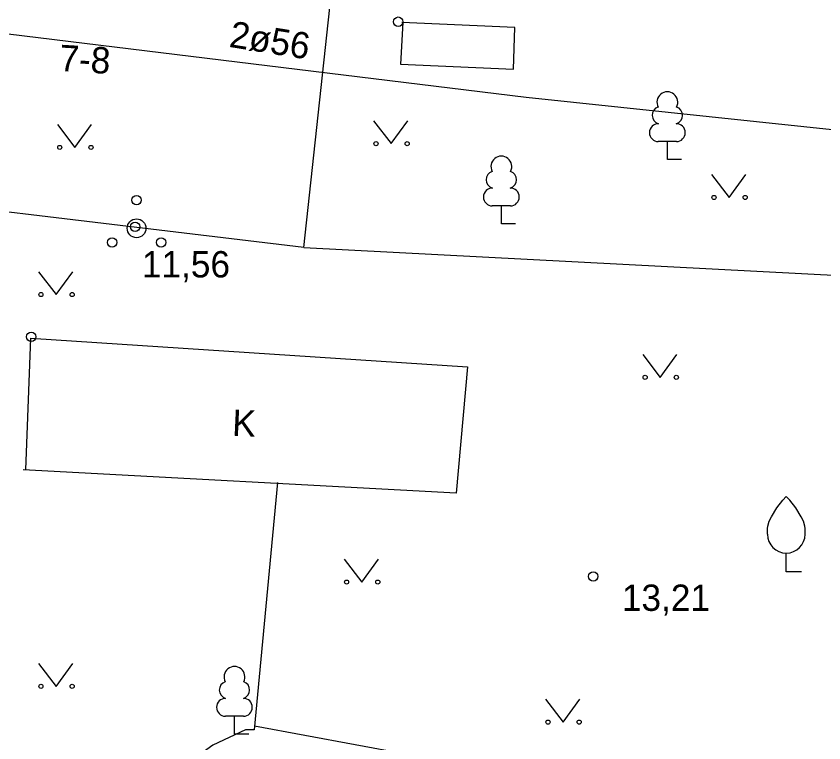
# Model space of a CAD drawing. Extents: x 713497 to 713863, y 6590062 to 6590327.
# Drawn here: x 713781.94 to 713803.4, y 6590278.31 to 6590297.62 of the extents above; entities that cross this region are included whole.
import ezdxf

# ---------------------------------------------------------------- set-up
doc = ezdxf.new("R2010")
doc.units = 0
for name, color, linetype in [('AED', 7, 'Continuous'), ('HALJASTUS', 7, 'Continuous'), ('HOONE', 7, 'Continuous'), ('KORGUS', 7, 'Continuous'), ('PUU', 7, 'Continuous'), ('RAJATIS', 7, 'Continuous'), ('TORU NR', 7, 'Continuous'), ('TTRASS', 7, 'Continuous')]:
    doc.layers.add(name, color=color, linetype=linetype)

msp = doc.modelspace()

# ---------------------------------------------------------------- linework, layer by layer
at = {"layer": 'AED'}
msp.add_lwpolyline([(713788.88, 6590285.23), (713788.26, 6590278.65), (713788.03, 6590278.65), (713787.17, 6590278.25), (713785.85, 6590277.29), (713784.83, 6590276.5), (713784.01, 6590275.55), (713783.55, 6590274.76), (713783.25, 6590274.03), (713776.26, 6590274.62), (713765.67, 6590275.3), (713754.93, 6590276.41), (713757.56, 6590281.99), (713749.75, 6590289.16), (713748.93, 6590295.3), (713750.19, 6590299.43)], dxfattribs=at)
at = {"layer": 'HALJASTUS'}
for p, q in [((713791.437, 6590294.837), (713791.9, 6590294.23)), ((713791.9, 6590294.23), (713792.346, 6590294.837)), ((713783.037, 6590294.737), (713783.5, 6590294.13)), ((713783.5, 6590294.13), (713783.946, 6590294.737)), ((713800.417, 6590293.407), (713800.88, 6590292.8)), ((713800.88, 6590292.8), (713801.326, 6590293.407)), ((713782.537, 6590290.827), (713783, 6590290.22)), ((713783, 6590290.22), (713783.446, 6590290.827)), ((713798.587, 6590288.627), (713799.05, 6590288.02)), ((713799.05, 6590288.02), (713799.496, 6590288.627)), ((713790.657, 6590283.187), (713791.12, 6590282.58)), ((713791.12, 6590282.58), (713791.566, 6590283.187)), ((713782.537, 6590280.417), (713783, 6590279.81)), ((713783, 6590279.81), (713783.446, 6590280.417)), ((713796.007, 6590279.467), (713796.47, 6590278.86)), ((713796.47, 6590278.86), (713796.916, 6590279.467))]:
    msp.add_line(p, q, dxfattribs=at)
msp.add_lwpolyline([(713835.82, 6590276.29), (713835.05, 6590276.56), (713830.82, 6590277.02), (713828.52, 6590277.18), (713826.1, 6590277.67), (713824.08, 6590277.83), (713822.14, 6590277.83), (713816.64, 6590278.64), (713814.22, 6590277.99), (713811.79, 6590277.2), (713807.92, 6590275.97), (713805.33, 6590275.41), (713802.91, 6590275.41), (713801.86, 6590275.65), (713801.29, 6590275.73), (713800.48, 6590276.13), (713798.54, 6590276.3), (713797.17, 6590276.7), (713794.83, 6590277.43), (713792.28, 6590278.01), (713788.27, 6590278.75)], dxfattribs=at)
for centre, radius in [((713783.099, 6590294.13), 0.055), ((713783.928, 6590294.13), 0.055), ((713791.499, 6590294.23), 0.055), ((713792.328, 6590294.23), 0.055), ((713785.14, 6590292.73), 0.125), ((713800.479, 6590292.8), 0.055), ((713801.308, 6590292.8), 0.055), ((713785.14, 6590291.98), 0.25), ((713784.49, 6590291.605), 0.125), ((713785.79, 6590291.605), 0.125), ((713782.599, 6590290.22), 0.055), ((713783.428, 6590290.22), 0.055), ((713798.649, 6590288.02), 0.055), ((713799.478, 6590288.02), 0.055), ((713790.719, 6590282.58), 0.055), ((713791.548, 6590282.58), 0.055), ((713782.599, 6590279.81), 0.055), ((713783.428, 6590279.81), 0.055), ((713796.069, 6590278.86), 0.055), ((713796.898, 6590278.86), 0.055)]:
    msp.add_circle(centre, radius, dxfattribs=at)
at = {"layer": 'HOONE'}
for points in [[(713789.58, 6590291.47), (713790.538, 6590300.306)], [(713789.58, 6590291.47), (713774.49, 6590293.28), (713770.41, 6590293.77)], [(713789.58, 6590291.47), (713819.58, 6590289.9)], [(713782.2, 6590285.56), (713782.33, 6590289.06), (713793.93, 6590288.3), (713793.63, 6590284.94), (713782.13, 6590285.56)]]:
    msp.add_lwpolyline(points, dxfattribs=at)
at = {"layer": 'KORGUS'}
for centre in [(713792.09, 6590297.47), (713785.1, 6590292.02), (713782.34, 6590289.1), (713797.27, 6590282.73)]:
    msp.add_circle(centre, 0.125, dxfattribs=at)
at = {"layer": 'PUU'}
for p, q in [((713799.48, 6590294.285), (713799, 6590294.285)), ((713799.24, 6590293.81), (713799.24, 6590294.285)), ((713799.62, 6590293.81), (713799.24, 6590293.81)), ((713795.07, 6590292.575), (713794.59, 6590292.575)), ((713794.83, 6590292.1), (713794.83, 6590292.575)), ((713795.21, 6590292.1), (713794.83, 6590292.1)), ((713802.4, 6590282.85), (713802.4, 6590283.35)), ((713802.8, 6590282.85), (713802.4, 6590282.85)), ((713787.98, 6590279.015), (713787.5, 6590279.015)), ((713787.74, 6590278.54), (713787.74, 6590279.015)), ((713788.12, 6590278.54), (713787.74, 6590278.54))]:
    msp.add_line(p, q, dxfattribs=at)
for points in [[(713801.9, 6590283.85), (713801.9, 6590284), (713801.91, 6590284.065), (713801.945, 6590284.195), (713802.005, 6590284.315), (713802.15, 6590284.55), (713802.31, 6590284.755), (713802.4, 6590284.85)], [(713802.9, 6590283.85), (713802.9, 6590284), (713802.89, 6590284.065), (713802.855, 6590284.195), (713802.795, 6590284.315), (713802.65, 6590284.55), (713802.49, 6590284.755), (713802.4, 6590284.85)]]:
    msp.add_lwpolyline(points, dxfattribs=at)
for centre, radius, start, end in [((713799.24, 6590295.33), 0.277, 332.5799, 207.4201), ((713799.07, 6590294.983), 0.233, 109.0217, 253.1415), ((713799.41, 6590294.983), 0.233, 286.8508, 70.9859), ((713799.003, 6590294.522), 0.238, 90.0016, 269.3953), ((713799.477, 6590294.522), 0.238, 270.6047, 89.9984), ((713794.83, 6590293.62), 0.277, 332.5799, 207.4201), ((713794.66, 6590293.273), 0.233, 109.0217, 253.1415), ((713795, 6590293.273), 0.233, 286.8508, 70.9859), ((713794.593, 6590292.812), 0.238, 90.0016, 269.3953), ((713795.067, 6590292.812), 0.238, 270.6047, 89.9984), ((713802.4, 6590283.85), 0.5, 180, 0), ((713787.74, 6590280.06), 0.277, 332.5799, 207.4201), ((713787.57, 6590279.713), 0.233, 109.0217, 253.1415), ((713787.91, 6590279.713), 0.233, 286.8508, 70.9859), ((713787.503, 6590279.252), 0.238, 90.0016, 269.3953), ((713787.977, 6590279.252), 0.238, 270.6047, 89.9984)]:
    msp.add_arc(centre, radius, start, end, dxfattribs=at)
at = {"layer": 'RAJATIS'}
msp.add_lwpolyline([(713792.21, 6590297.45), (713792.15, 6590296.34), (713795.15, 6590296.21), (713795.19, 6590297.32), (713792.19, 6590297.45)], dxfattribs=at)
at = {"layer": 'TTRASS'}
msp.add_lwpolyline([(713863.358, 6590288.356), (713837.4, 6590291.03), (713795.49, 6590295.46), (713781.73, 6590297.14)], dxfattribs=at)

# ---------------------------------------------------------------- texts
at = {"layer": 'HOONE'}
msp.add_text('K', height=0.7, rotation=357.383, dxfattribs=at).set_placement((713787.668, 6590286.47))
at = {"layer": 'KORGUS'}
for s, p in [('11,56', (713785.28, 6590290.675)), ('13,21', (713798.032, 6590281.815))]:
    msp.add_text(s, height=0.7, dxfattribs=at).set_placement(p)
at = {"layer": 'TORU NR'}
for s, rotation, p in [('2ø56', 350.8375, (713787.576, 6590296.804)), ('7-8', 356.6326, (713783.074, 6590296.161))]:
    msp.add_text(s, height=0.7, rotation=rotation, dxfattribs=at).set_placement(p)

doc.saveas('drawing.dxf')
